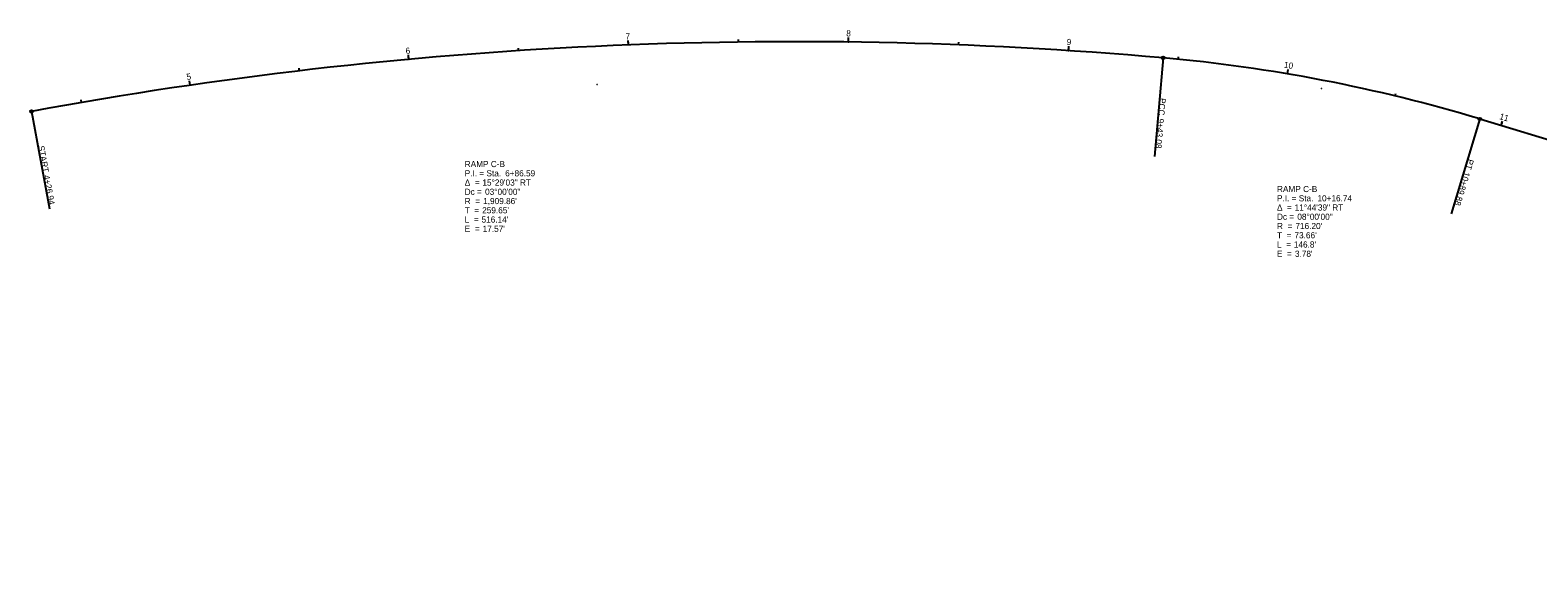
# Model space of a CAD drawing. Extents: x 2196454 to 2197821, y 661371 to 661616.
# Drawn here: x 2196454 to 2197139, y 661372 to 661616 of the extents above; entities that cross this region are included whole.
import ezdxf

# ---------------------------------------------------------------- set-up
doc = ezdxf.new("R2010")
doc.units = 0
for name, color, linetype in [('Default', 7, 'Continuous'), ('GE_X_Alignment', 7, 'Continuous'), ('GE_X_Alignment_1000_Stations', 7, 'Continuous'), ('GE_X_Alignment_100_Curve_Data', 7, 'Continuous'), ('GE_X_Alignment_100_Stations', 7, 'Continuous'), ('GE_X_Alignment_500_Stations', 7, 'Continuous')]:
    doc.layers.add(name, color=color, linetype=linetype)

msp = doc.modelspace()

# ---------------------------------------------------------------- linework, layer by layer
at = {"layer": 'Default'}
for centre in [(2196726.13, 661609.52), (2196826.11, 661610.84), (2196626.35, 661602.98), (2196926.02, 661606.92), (2196968.97, 661603.62), (2196968.97, 661603.62), (2196968.97, 661603.62), (2197025.41, 661596.38), (2197025.41, 661596.38), (2197025.41, 661596.38), (2196527.06, 661591.22), (2196527.06, 661591.22), (2196711.97, 661591.49), (2196711.97, 661591.49), (2196711.97, 661591.49), (2197040.91, 661589.76), (2197040.91, 661589.76), (2197040.91, 661589.76), (2196454.97, 661579.35), (2196454.97, 661579.35), (2196454.97, 661579.35), (2197112.86, 661575.89), (2197112.86, 661575.89), (2197112.86, 661575.89), (2197122.55, 661572.97)]:
    msp.add_circle(centre, 0.0000833, dxfattribs=at)
at = {"layer": 'GE_X_Alignment'}
msp.add_line((2197112.86, 661575.89), (2197790.31, 661371.59), dxfattribs=at)
for centre, radius, start, end in [((2196801.25, 659701.14), 1909.86, 84.9622, 100.44626), ((2196906.08, 660890.19), 716.2, 73.21807, 84.96233)]:
    msp.add_arc(centre, radius, start, end, dxfattribs=at)
at = {"layer": 'GE_X_Alignment_1000_Stations'}
for p, q in [((2196968.97, 661603.62), (2196965.01, 661558.8)), ((2197025.41, 661596.38), (2197025.74, 661598.35)), ((2196527.06, 661591.22), (2196526.88, 661592.4)), ((2196454.97, 661579.35), (2196463.13, 661535.09)), ((2197112.86, 661575.89), (2197099.87, 661532.81))]:
    msp.add_line(p, q, dxfattribs=at)
for centre in [(2196968.97, 661603.62), (2196454.97, 661579.35), (2197112.86, 661575.89)]:
    msp.add_circle(centre, 0.6, dxfattribs=at)
at = {"layer": 'GE_X_Alignment_100_Stations'}
for p, q in [((2196676.2, 661606.9), (2196676.12, 661608.1)), ((2196726.13, 661609.52), (2196726.05, 661611.52)), ((2196776.11, 661610.84), (2196776.09, 661612.04)), ((2196826.11, 661610.84), (2196826.13, 661612.84)), ((2196876.09, 661609.54), (2196876.13, 661610.73)), ((2196926.02, 661606.92), (2196926.15, 661608.92)), ((2196626.35, 661602.98), (2196626.17, 661604.97)), ((2196968.97, 661603.62), (2196965.01, 661558.8)), ((2196975.86, 661602.98), (2196975.98, 661604.18)), ((2196576.63, 661597.75), (2196576.49, 661598.94)), ((2197025.41, 661596.38), (2197025.74, 661598.35)), ((2196527.06, 661591.22), (2196526.77, 661593.2)), ((2197074.38, 661586.33), (2197074.66, 661587.5)), ((2196477.67, 661583.39), (2196477.47, 661584.57)), ((2196454.97, 661579.35), (2196463.13, 661535.09)), ((2197112.86, 661575.89), (2197099.87, 661532.81)), ((2197122.55, 661572.97), (2197123.13, 661574.88))]:
    msp.add_line(p, q, dxfattribs=at)
for centre in [(2196968.97, 661603.62), (2196454.97, 661579.35), (2197112.86, 661575.89)]:
    msp.add_circle(centre, 0.6, dxfattribs=at)
at = {"layer": 'GE_X_Alignment_500_Stations'}
for p, q in [((2196726.13, 661609.52), (2196726.08, 661610.72)), ((2196826.11, 661610.84), (2196826.12, 661612.04)), ((2196926.02, 661606.92), (2196926.1, 661608.12)), ((2196626.35, 661602.98), (2196626.24, 661604.17)), ((2196968.97, 661603.62), (2196965.01, 661558.8)), ((2197025.41, 661596.38), (2197025.74, 661598.35)), ((2196527.06, 661591.22), (2196526.77, 661593.2)), ((2196454.97, 661579.35), (2196463.13, 661535.09)), ((2197112.86, 661575.89), (2197099.87, 661532.81)), ((2197122.55, 661572.97), (2197122.9, 661574.12))]:
    msp.add_line(p, q, dxfattribs=at)
for centre in [(2196968.97, 661603.62), (2196454.97, 661579.35), (2197112.86, 661575.89)]:
    msp.add_circle(centre, 0.6, dxfattribs=at)

# ---------------------------------------------------------------- texts
at = {"layer": 'GE_X_Alignment_1000_Stations'}
for s, rotation, p in [('10', 350.40839, (2197023.67, 661599.26)), ('PCC', 264.96233, (2196967.41, 661585.5)), ('9+43.08', 264.96233, (2196966.59, 661576.19)), ('START', 280.44626, (2196457.94, 661563.5)), ('PT', 253.21826, (2197107.5, 661557.94)), ('4+26.94', 280.44626, (2196460.4, 661550.17)), ('10+89.88', 253.21826, (2197105.74, 661552.11))]:
    msp.add_text(s, height=2.8, rotation=rotation, dxfattribs=at).set_placement(p)
at = {"layer": 'GE_X_Alignment_100_Curve_Data'}
for s, p in [('RAMP C-B', (2196651.75, 661554.03)), ('Δ  = ', (2196651.75, 661545.63)), ('P.I. = Sta. ', (2196651.75, 661549.83)), ('15°29\'03" RT', (2196659.77, 661545.63)), ('6+86.59', (2196670.12, 661549.83)), ('Dc = ', (2196651.75, 661541.43)), ('R  = ', (2196651.75, 661537.23)), ("1,909.86'", (2196660.12, 661537.23)), ('03°00\'00"', (2196660.99, 661541.43)), ('RAMP C-B', (2197020.69, 661542.69)), ('P.I. = Sta. ', (2197020.69, 661538.49)), ('10+16.74', (2197039.06, 661538.49)), ('T  = ', (2196651.75, 661533.03)), ("259.65'", (2196659.68, 661533.03)), ('Δ  = ', (2197020.69, 661534.29)), ('Dc = ', (2197020.69, 661530.09)), ('11°44\'39" RT', (2197028.71, 661534.29)), ('08°00\'00"', (2197029.93, 661530.09)), ('L  = ', (2196651.75, 661528.83)), ('E  = ', (2196651.75, 661524.63)), ("516.14'", (2196659.4, 661528.83)), ("17.57'", (2196659.9, 661524.63)), ('R  = ', (2197020.69, 661525.89)), ("716.20'", (2197029.06, 661525.89)), ('T  = ', (2197020.69, 661521.69)), ('L  = ', (2197020.69, 661517.49)), ("146.8'", (2197028.34, 661517.49)), ("73.66'", (2197028.62, 661521.69)), ('E  = ', (2197020.69, 661513.29)), ("3.78'", (2197028.84, 661513.29))]:
    msp.add_text(s, height=2.8, dxfattribs=at).set_placement(p)
at = {"layer": 'GE_X_Alignment_100_Stations'}
for s, rotation, p in [('7', 2.25446, (2196724.86, 661611.98)), ('8', 359.25446, (2196825.04, 661613.4)), ('6', 5.25446, (2196625.01, 661605.41)), ('9', 356.25446, (2196925.11, 661609.53)), ('10', 350.40839, (2197023.67, 661599.26)), ('5', 8.25446, (2196525.58, 661593.58)), ('PCC', 264.96233, (2196967.41, 661585.5)), ('9+43.08', 264.96233, (2196966.59, 661576.19)), ('11', 343.21826, (2197121.48, 661575.9)), ('START', 280.44626, (2196457.94, 661563.5)), ('PT', 253.21826, (2197107.5, 661557.94)), ('4+26.94', 280.44626, (2196460.4, 661550.17)), ('10+89.88', 253.21826, (2197105.74, 661552.11))]:
    msp.add_text(s, height=2.8, rotation=rotation, dxfattribs=at).set_placement(p)
at = {"layer": 'GE_X_Alignment_500_Stations'}
for s, rotation, p in [('10', 350.40839, (2197023.67, 661599.26)), ('5', 8.25446, (2196525.58, 661593.58)), ('PCC', 264.96233, (2196967.41, 661585.5)), ('9+43.08', 264.96233, (2196966.59, 661576.19)), ('START', 280.44626, (2196457.94, 661563.5)), ('PT', 253.21826, (2197107.5, 661557.94)), ('4+26.94', 280.44626, (2196460.4, 661550.17)), ('10+89.88', 253.21826, (2197105.74, 661552.11))]:
    msp.add_text(s, height=2.8, rotation=rotation, dxfattribs=at).set_placement(p)

doc.saveas('drawing.dxf')
